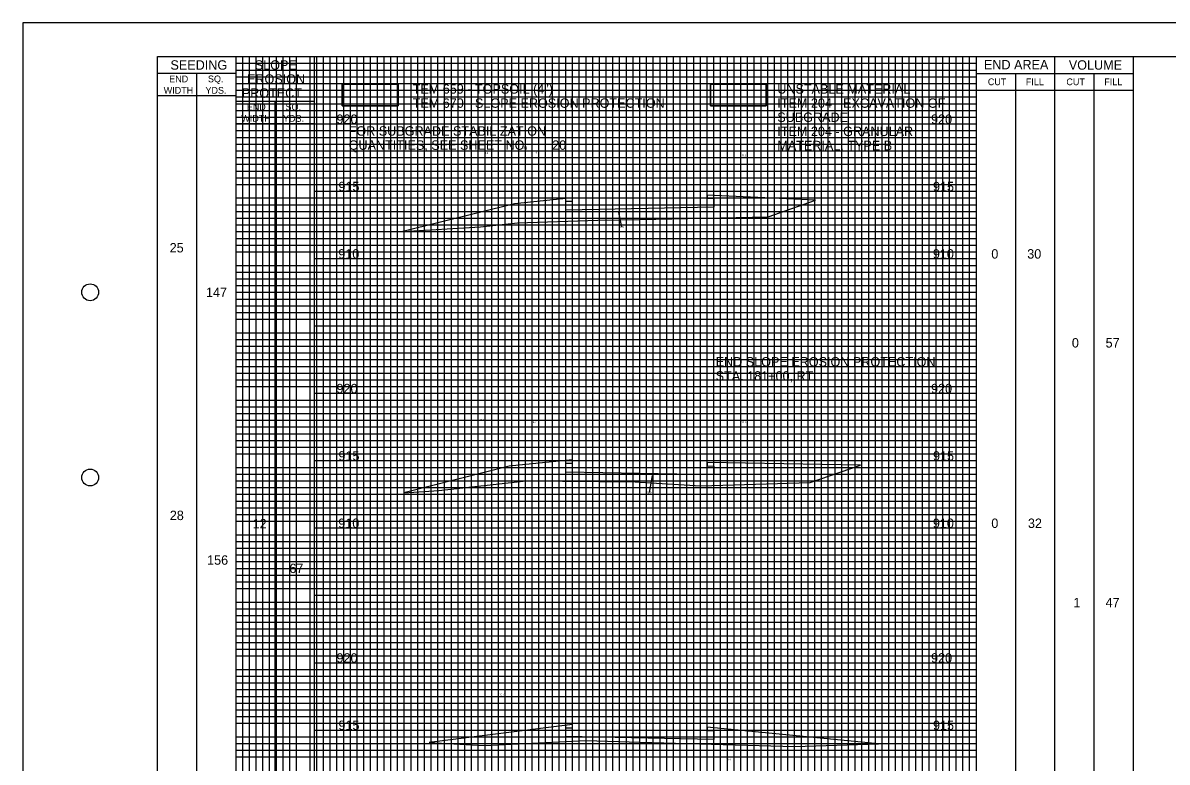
# Model space of a CAD drawing. Extents: x -73 to 160, y -2 to 1877.
# Drawn here: x -10 to 75, y 857.6 to 912.5 of the extents above; entities that cross this region are included whole.
import ezdxf

# ---------------------------------------------------------------- set-up
doc = ezdxf.new("R2010")
doc.units = 0
for name, color, linetype in [('DR_P_Flood_Boundary', 7, 'Continuous'), ('GK_Cells', 7, 'Continuous'), ('PV_P_Drive', 7, 'Continuous'), ('PV_P_EOP', 7, 'Continuous'), ('RD_X_Fence', 7, 'Continuous'), ('TX_X_5', 7, 'Continuous'), ('UT_P_Water_Cells', 7, 'Continuous'), ('XS_P_Pavt_Surface', 7, 'Continuous'), ('XS_P_Special_Benching', 7, 'Continuous'), ('XS_X_Ground_Line', 7, 'Continuous')]:
    doc.layers.add(name, color=color, linetype=linetype)

msp = doc.modelspace()

# ---------------------------------------------------------------- linework, layer by layer
at = {"layer": 'DR_P_Flood_Boundary'}
for p, q in [((15.832, 805), (15.832, 910)), ((20.832, 805), (20.832, 910)), ((25.832, 805), (25.832, 910)), ((30.832, 805), (30.832, 910)), ((35.832, 805), (35.832, 910)), ((40.832, 805), (40.832, 910)), ((45.832, 805), (45.832, 910)), ((50.832, 805), (50.832, 910)), ((55.832, 805), (55.832, 910)), ((5.832, 905), (60.832, 905)), ((11.665, 900), (60.832, 900)), ((11.665, 895), (60.832, 895)), ((11.665, 890), (60.832, 890)), ((11.665, 885), (60.832, 885)), ((11.665, 880), (60.832, 880)), ((11.665, 875), (60.832, 875)), ((11.665, 870), (60.832, 870)), ((11.665, 865), (60.832, 865)), ((11.665, 860), (60.832, 860))]:
    msp.add_line(p, q, dxfattribs=at)
at = {"layer": 'GK_Cells'}
msp.add_lwpolyline([(0, 910), (157.5, 910), (157.5, 805), (0, 805)], close=True, dxfattribs=at)
for centre in [(-5, 892.5), (-5, 878.75)]:
    msp.add_circle(centre, 0.625, dxfattribs=at)
at = {"layer": 'PV_P_Drive'}
msp.add_lwpolyline([(13.726, 907.961), (17.867, 907.961), (17.867, 906.346), (13.726, 906.346)], close=True, dxfattribs=at)
msp.add_lwpolyline([(13.726, 906.346), (17.867, 906.346), (17.867, 907.961), (13.726, 907.961), (13.726, 906.346)], dxfattribs=at)
at = {"layer": 'PV_P_EOP'}
msp.add_lwpolyline([(41.075, 907.961), (45.216, 907.961), (45.216, 906.346), (41.075, 906.346)], close=True, dxfattribs=at)
msp.add_lwpolyline([(41.075, 906.346), (45.216, 906.346), (45.216, 907.961), (41.075, 907.961), (41.075, 906.346)], dxfattribs=at)
at = {"layer": 'RD_X_Fence'}
for p, q in [((30.832, 899.518), (26.51, 899.074)), ((48.877, 899.331), (40.832, 899.718)), ((40.832, 899.468), (41.332, 899.478)), ((41.332, 899.478), (41.332, 898.811)), ((26.51, 899.074), (18.214, 897)), ((30.332, 899.258), (30.832, 899.268)), ((30.332, 898.591), (30.332, 899.258)), ((41.332, 898.811), (30.332, 898.591)), ((34.242, 898.424), (34.477, 897.352)), ((30.832, 880.061), (26.135, 879.578)), ((30.332, 879.154), (30.332, 879.821)), ((30.332, 879.821), (30.832, 879.811)), ((52.218, 879.669), (40.832, 879.861)), ((26.135, 879.578), (18.29, 877.617)), ((41.332, 878.934), (30.332, 879.154)), ((36.757, 878.904), (36.52, 877.64)), ((40.832, 879.611), (41.332, 879.601)), ((41.332, 879.601), (41.332, 878.934)), ((30.832, 860.414), (20.183, 859.067)), ((53.55, 858.968), (40.832, 860.214)), ((30.332, 859.508), (30.332, 860.174)), ((30.332, 860.174), (30.832, 860.164)), ((41.332, 859.288), (30.332, 859.508)), ((40.832, 859.964), (41.332, 859.954)), ((41.332, 859.954), (41.332, 859.288))]:
    msp.add_line(p, q, dxfattribs=at)
for points in [[(18.214, 897), (23.999, 897.37), (26.747, 897.651), (32.711, 897.844), (35.832, 897.907), (45.37, 898.097), (48.877, 899.331)], [(30.832, 899.268), (30.832, 899.414), (30.832, 899.518)], [(40.832, 899.718), (40.832, 899.614), (40.832, 899.468)], [(30.832, 879.811), (30.832, 879.957), (30.832, 880.061)], [(40.832, 879.861), (40.832, 879.757), (40.832, 879.611)], [(18.29, 877.617), (20.889, 877.788), (27.389, 878.492), (35.49, 878.432), (35.833, 878.411), (40.358, 878.137), (48.48, 878.371), (52.218, 879.669)], [(30.832, 860.164), (30.832, 860.31), (30.832, 860.414)], [(40.832, 860.214), (40.832, 860.11), (40.832, 859.964)], [(20.183, 859.067), (24.3, 858.845), (31.835, 859.219), (35.832, 859.106), (47.335, 858.784), (53.55, 858.968)]]:
    msp.add_lwpolyline(points, dxfattribs=at)
at = {"layer": 'TX_X_5'}
msp.add_lwpolyline([(-10, 802.5), (160, 802.5), (160, 912.5), (-10, 912.5)], close=True, dxfattribs=at)
at = {"layer": 'UT_P_Water_Cells'}
for p, q in [((5.832, 909.5), (60.832, 909.5)), ((6.332, 805), (6.332, 910)), ((6.832, 805), (6.832, 910)), ((7.332, 805), (7.332, 910)), ((7.832, 805), (7.832, 910)), ((8.332, 805), (8.332, 910)), ((8.832, 805), (8.832, 910)), ((9.332, 805), (9.332, 910)), ((9.832, 805), (9.832, 910)), ((10.332, 805), (10.332, 910)), ((11.332, 805), (11.332, 910)), ((11.832, 805), (11.832, 910)), ((12.332, 805), (12.332, 910)), ((12.832, 805), (12.832, 910)), ((13.332, 805), (13.332, 910)), ((13.832, 805), (13.832, 910)), ((14.332, 805), (14.332, 910)), ((14.832, 805), (14.832, 910)), ((15.332, 805), (15.332, 910)), ((16.332, 805), (16.332, 910)), ((16.832, 805), (16.832, 910)), ((17.332, 805), (17.332, 910)), ((17.832, 805), (17.832, 910)), ((18.332, 805), (18.332, 910)), ((18.832, 805), (18.832, 910)), ((19.332, 805), (19.332, 910)), ((19.832, 805), (19.832, 910)), ((20.332, 805), (20.332, 910)), ((21.332, 805), (21.332, 910)), ((21.832, 805), (21.832, 910)), ((22.332, 805), (22.332, 910)), ((22.832, 805), (22.832, 910)), ((23.332, 805), (23.332, 910)), ((23.832, 805), (23.832, 910)), ((24.332, 805), (24.332, 910)), ((24.832, 805), (24.832, 910)), ((25.332, 805), (25.332, 910)), ((26.332, 805), (26.332, 910)), ((26.832, 805), (26.832, 910)), ((27.332, 805), (27.332, 910)), ((27.832, 805), (27.832, 910)), ((28.332, 805), (28.332, 910)), ((28.832, 805), (28.832, 910)), ((29.332, 805), (29.332, 910)), ((29.832, 805), (29.832, 910)), ((30.332, 805), (30.332, 910)), ((31.332, 805), (31.332, 910)), ((31.832, 805), (31.832, 910)), ((32.332, 805), (32.332, 910)), ((32.832, 805), (32.832, 910)), ((33.332, 805), (33.332, 910)), ((33.832, 805), (33.832, 910)), ((34.332, 805), (34.332, 910)), ((34.832, 805), (34.832, 910)), ((35.332, 805), (35.332, 910)), ((36.332, 805), (36.332, 910)), ((36.832, 805), (36.832, 910)), ((37.332, 805), (37.332, 910)), ((37.832, 805), (37.832, 910)), ((38.332, 805), (38.332, 910)), ((38.832, 805), (38.832, 910)), ((39.332, 805), (39.332, 910)), ((39.832, 805), (39.832, 910)), ((40.332, 805), (40.332, 910)), ((41.332, 805), (41.332, 910)), ((41.832, 805), (41.832, 910)), ((42.332, 805), (42.332, 910)), ((42.832, 805), (42.832, 910)), ((43.332, 805), (43.332, 910)), ((43.832, 805), (43.832, 910)), ((44.332, 805), (44.332, 910)), ((44.832, 805), (44.832, 910)), ((45.332, 805), (45.332, 910)), ((46.332, 805), (46.332, 910)), ((46.832, 805), (46.832, 910)), ((47.332, 805), (47.332, 910)), ((47.832, 805), (47.832, 910)), ((48.332, 805), (48.332, 910)), ((48.832, 805), (48.832, 910)), ((49.332, 805), (49.332, 910)), ((49.832, 805), (49.832, 910)), ((50.332, 805), (50.332, 910)), ((51.332, 805), (51.332, 910)), ((51.832, 805), (51.832, 910)), ((52.332, 805), (52.332, 910)), ((52.832, 805), (52.832, 910)), ((53.332, 805), (53.332, 910)), ((53.832, 805), (53.832, 910)), ((54.332, 805), (54.332, 910)), ((54.832, 805), (54.832, 910)), ((55.332, 805), (55.332, 910)), ((56.332, 805), (56.332, 910)), ((56.832, 805), (56.832, 910)), ((57.332, 805), (57.332, 910)), ((57.832, 805), (57.832, 910)), ((58.332, 805), (58.332, 910)), ((58.832, 805), (58.832, 910)), ((59.332, 805), (59.332, 910)), ((59.832, 805), (59.832, 910)), ((60.332, 805), (60.332, 910)), ((5.832, 909), (60.832, 909)), ((5.832, 908.5), (60.832, 908.5)), ((5.832, 908), (60.832, 908)), ((5.832, 907.5), (60.832, 907.5)), ((5.832, 907), (60.832, 907)), ((5.832, 906.5), (60.832, 906.5)), ((5.832, 906), (60.832, 906)), ((5.832, 905.5), (60.832, 905.5)), ((5.832, 904.5), (60.832, 904.5)), ((5.832, 904), (60.832, 904)), ((5.832, 903.5), (60.832, 903.5)), ((5.832, 903), (60.832, 903)), ((5.832, 902.5), (60.832, 902.5)), ((5.832, 902), (60.832, 902)), ((5.832, 901.5), (60.832, 901.5)), ((5.832, 901), (60.832, 901)), ((5.832, 900.5), (60.832, 900.5)), ((5.832, 899.5), (60.832, 899.5)), ((5.832, 899), (60.832, 899)), ((5.832, 898.5), (60.832, 898.5)), ((5.832, 898), (60.832, 898)), ((5.832, 897.5), (60.832, 897.5)), ((5.832, 897), (60.832, 897)), ((5.832, 896.5), (60.832, 896.5)), ((5.832, 896), (60.832, 896)), ((5.832, 895.5), (60.832, 895.5)), ((5.832, 894.5), (60.832, 894.5)), ((5.832, 894), (60.832, 894)), ((5.832, 893.5), (60.832, 893.5)), ((5.832, 893), (60.832, 893)), ((5.832, 892.5), (60.832, 892.5)), ((5.832, 892), (60.832, 892)), ((5.832, 891.5), (60.832, 891.5)), ((5.832, 891), (60.832, 891)), ((5.832, 890.5), (60.832, 890.5)), ((5.832, 889.5), (60.832, 889.5)), ((5.832, 889), (60.832, 889)), ((5.832, 888.5), (60.832, 888.5)), ((5.832, 888), (60.832, 888)), ((5.832, 887.5), (60.832, 887.5)), ((5.832, 887), (60.832, 887)), ((5.832, 886.5), (60.832, 886.5)), ((5.832, 886), (60.832, 886)), ((5.832, 885.5), (60.832, 885.5)), ((5.832, 884.5), (60.832, 884.5)), ((5.832, 884), (60.832, 884)), ((5.832, 883.5), (60.832, 883.5)), ((5.832, 883), (60.832, 883)), ((5.832, 882.5), (60.832, 882.5)), ((5.832, 882), (60.832, 882)), ((5.832, 881.5), (60.832, 881.5)), ((5.832, 881), (60.832, 881)), ((5.832, 880.5), (60.832, 880.5)), ((5.832, 879.5), (60.832, 879.5)), ((5.832, 879), (60.832, 879)), ((5.832, 878.5), (60.832, 878.5)), ((5.832, 878), (60.832, 878)), ((5.832, 877.5), (60.832, 877.5)), ((5.832, 877), (60.832, 877)), ((5.832, 876.5), (60.832, 876.5)), ((5.832, 876), (60.832, 876)), ((5.832, 875.5), (60.832, 875.5)), ((5.832, 874.5), (60.832, 874.5)), ((5.832, 874), (60.832, 874)), ((5.832, 873.5), (60.832, 873.5)), ((5.832, 873), (60.832, 873)), ((5.832, 872.5), (60.832, 872.5)), ((5.832, 872), (60.832, 872)), ((5.832, 871.5), (60.832, 871.5)), ((5.832, 871), (60.832, 871)), ((5.832, 870.5), (60.832, 870.5)), ((5.832, 869.5), (60.832, 869.5)), ((5.832, 869), (60.832, 869)), ((5.832, 868.5), (60.832, 868.5)), ((5.832, 868), (60.832, 868)), ((5.832, 867.5), (60.832, 867.5)), ((5.832, 867), (60.832, 867)), ((5.832, 866.5), (60.832, 866.5)), ((5.832, 866), (60.832, 866)), ((5.832, 865.5), (60.832, 865.5)), ((5.832, 864.5), (60.832, 864.5)), ((5.832, 864), (60.832, 864)), ((5.832, 863.5), (60.832, 863.5)), ((5.832, 863), (60.832, 863)), ((5.832, 862.5), (60.832, 862.5)), ((5.832, 862), (60.832, 862)), ((5.832, 861.5), (60.832, 861.5)), ((5.832, 861), (60.832, 861)), ((5.832, 860.5), (60.832, 860.5)), ((5.832, 859.5), (60.832, 859.5)), ((5.832, 859), (60.832, 859)), ((5.832, 858.5), (60.832, 858.5)), ((5.832, 858), (60.832, 858))]:
    msp.add_line(p, q, dxfattribs=at)
at = {"layer": 'XS_X_Ground_Line'}
for p, q in [((5.832, 805), (5.832, 910)), ((5.832, 805), (5.832, 910)), ((11.665, 805), (11.665, 910)), ((60.832, 805), (60.832, 910)), ((66.667, 805), (66.667, 910)), ((72.5, 805), (72.5, 910)), ((5.832, 908.75), (0, 908.75)), ((2.916, 805), (2.916, 908.75)), ((60.832, 908.75), (72.5, 908.75)), ((63.75, 805), (63.75, 908.75)), ((69.583, 805), (69.583, 908.75)), ((5.832, 907.083), (0, 907.083)), ((60.832, 907.5), (72.5, 907.5)), ((11.665, 906.667), (5.832, 906.667)), ((8.749, 805), (8.749, 906.667)), ((11.665, 905), (5.832, 905))]:
    msp.add_line(p, q, dxfattribs=at)

# ---------------------------------------------------------------- texts
at = {"layer": 'RD_X_Fence'}
for s, p in [('8.6', (24.299, 902.763)), ('11.9', (27.079, 903.197)), ('4.3', (28.084, 902.797)), ('8.1', (43.436, 902.6)), ('29.9', (34.27, 897.282)), ('8.1', (23.991, 882.945)), ('4.7', (27.88, 882.787)), ('11.4', (43.374, 882.787)), ('32.0', (36.307, 877.57)), ('10.7', (25.392, 862.565)), ('12.8', (43.037, 862.414)), ('19.4', (42.2, 857.737))]:
    msp.add_text(s, height=0.14, dxfattribs=at).set_placement(p)
at = {"layer": 'XS_P_Pavt_Surface'}
for s, p in [('920', (13.298, 905)), ('920', (57.465, 905)), ('915', (13.441, 900)), ('915', (57.609, 900)), ('25', (0.904, 895.458)), ('910', (13.43, 895)), ('910', (57.598, 895)), ('0', (61.941, 895)), ('30', (64.609, 895)), ('147', (3.6, 892.142)), ('0', (67.925, 888.396)), ('57', (70.43, 888.396)), ('END SLOPE EROSION PROTECTION', (41.465, 886.99)), ('STA. 181+00, RT.', (41.465, 885.94)), ('920', (13.298, 885)), ('920', (57.465, 885)), ('915', (13.441, 880)), ('915', (57.609, 880)), ('28', (0.915, 875.588)), ('12', (7.065, 874.968)), ('910', (13.43, 875)), ('910', (57.598, 875)), ('0', (61.941, 875)), ('32', (64.661, 875)), ('156', (3.685, 872.271)), ('67', (9.799, 871.652)), ('1', (68.04, 869.112)), ('47', (70.427, 869.112)), ('920', (13.298, 865)), ('920', (57.465, 865)), ('915', (13.441, 860)), ('915', (57.609, 860))]:
    msp.add_text(s, height=0.7, dxfattribs=at).set_placement(p)
at = {"layer": 'XS_P_Special_Benching'}
for s, p in [('ITEM 659 - TOPSOIL (4")', (18.694, 907.247)), ('UNSTABLE MATERIAL', (46.043, 907.247)), ('ITEM 670 - SLOPE EROSION PROTECTION', (18.694, 906.197)), ('ITEM 204 - EXCAVATION OF', (46.043, 906.197)), ('SUBGRADE', (46.043, 905.147)), ('FOR SUBGRADE STABILIZATION', (14.202, 904.127)), ('ITEM 204 - GRANULAR', (46.043, 904.097)), ('QUANTITIES, SEE SHEET NO.', (14.202, 903.077)), ('20', (29.32, 903.077)), ('MATERIAL, TYPE B', (46.043, 903.047))]:
    msp.add_text(s, height=0.7, dxfattribs=at).set_placement(p)
at = {"layer": 'XS_X_Ground_Line'}
for s, height, p in [('SEEDING', 0.7, (0.964, 909.025)), ('SLOPE', 0.7, (7.228, 909.025)), ('END AREA', 0.7, (61.394, 909.047)), ('VOLUME', 0.7, (67.698, 909.025)), ('EROSION', 0.7, (6.649, 907.983)), ('END', 0.5, (0.87, 908.092)), ('SQ.', 0.5, (3.748, 908.092)), ('CUT', 0.5, (61.683, 907.875)), ('FILL', 0.5, (64.502, 907.875)), ('CUT', 0.5, (67.517, 907.875)), ('FILL', 0.5, (70.335, 907.875)), ('WIDTH', 0.5, (0.462, 907.242)), ('YDS.', 0.5, (3.563, 907.242)), ('PROTECT.', 0.7, (6.26, 906.942)), ('END', 0.5, (6.631, 906.008)), ('SQ.', 0.5, (9.51, 906.008)), ('WIDTH', 0.5, (6.224, 905.158)), ('YDS.', 0.5, (9.325, 905.158))]:
    msp.add_text(s, height=height, dxfattribs=at).set_placement(p)

doc.saveas('drawing.dxf')
